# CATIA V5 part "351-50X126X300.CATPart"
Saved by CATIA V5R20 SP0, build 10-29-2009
Part number: 351-50X126X300
Definition: NONE
Nomenclature: 351-50X126X300
Source: Unknown
Description: 351-50X126X300
Bounding box of the stored display mesh (mm): x -10 to 290, y -32.5 to 32.5, z -32.5 to 32.5
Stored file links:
  C:\Users\Utente\Desktop\IO LAVORO\3D X SITO CF\X SITO\PLASTICA\351\351-50X126X300.CATPart
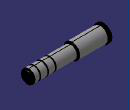
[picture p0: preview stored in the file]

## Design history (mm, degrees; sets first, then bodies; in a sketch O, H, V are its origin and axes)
Body1 "351-50X126X300" (main body)
  Solid1: solid without history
